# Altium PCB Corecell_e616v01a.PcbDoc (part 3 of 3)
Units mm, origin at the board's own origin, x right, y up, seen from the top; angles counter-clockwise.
Board outline 72.95 x 30.9 mm, 4 copper layers (Top Layer, MidLayer1 - GND, MidLayer2, Bottom Layer), stack 0.637 mm thick; 233 components, 174 nets, 666 pads, 1160 vias.
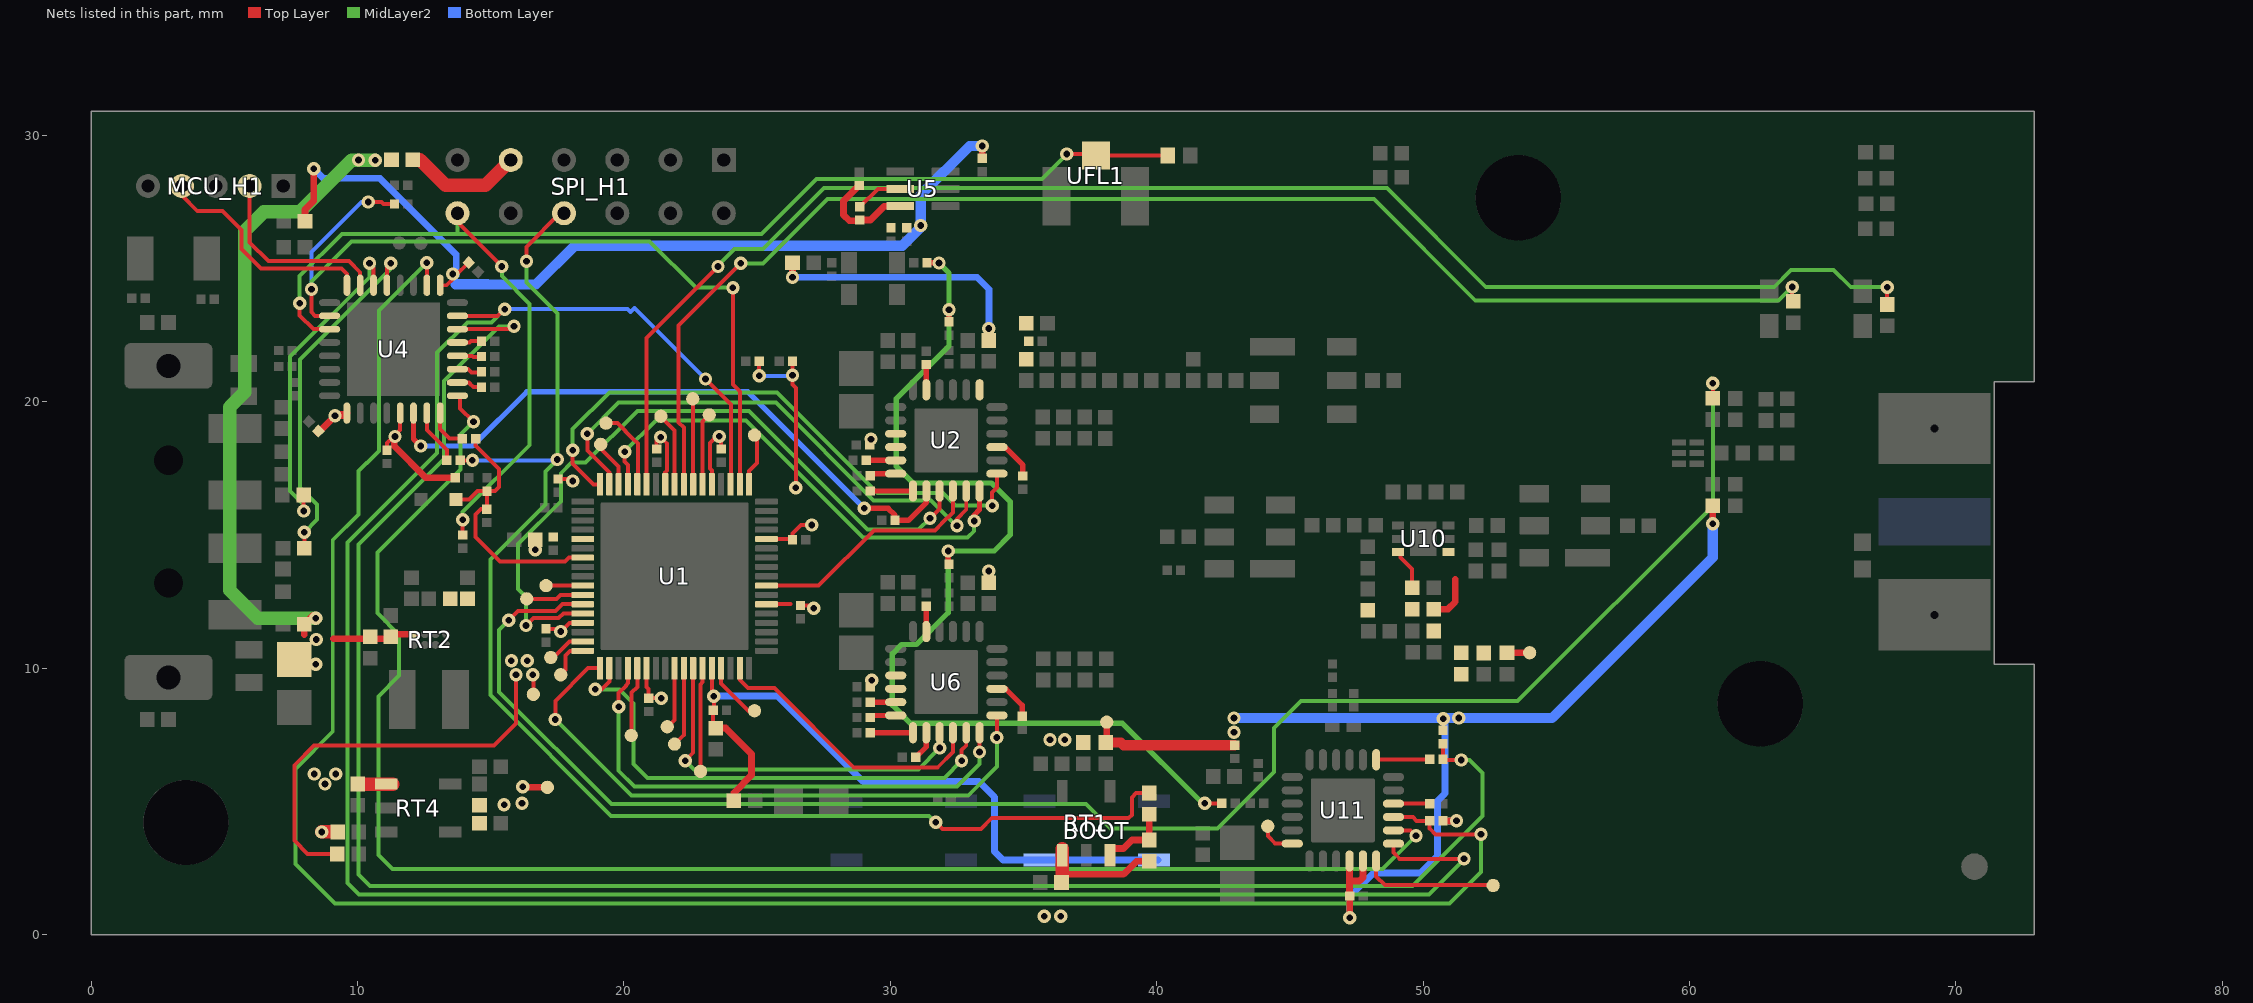
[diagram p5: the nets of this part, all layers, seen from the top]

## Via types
v1: diameter 0.5, hole 0.25, Top Layer to Bottom Layer, tented both sides, 1086 vias
v2: diameter 0.6, hole 0.3, Top Layer to Bottom Layer, tented top, 49 vias
v3: diameter 0.5, hole 0.25, Top Layer to Bottom Layer, 16 vias
v4: diameter 0.5, hole 0.2, Top Layer to Bottom Layer, 9 vias

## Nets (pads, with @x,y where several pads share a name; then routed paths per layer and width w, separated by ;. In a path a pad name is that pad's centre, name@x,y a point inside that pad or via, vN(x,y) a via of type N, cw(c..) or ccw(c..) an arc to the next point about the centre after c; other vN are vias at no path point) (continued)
NetR35_1: R35.1 U4.8 | length 1.6
  Top Layer w0.15: U4.8@13.1,19.575 13.1,18.975 13.457,18.618 R35.1@13.93,18.618
NetR37_2: R37.2 U4.13 | length 0.9
  Top Layer w0.15: U4.13@13.75,22.225 14.2,22.225 14.25,22.275 R37.2@14.65,22.275
NetR39_2: R39.2 R40.1 RT1.3 | length 2.6
  Top Layer w0.254: RT1.3@38.249,3.229 38.751,3.229 39.072,3.55 R39.2@39.717,3.55 R40.1@39.717,4.512
NetR48_1: R48.1 U4.10 | length 1
  Top Layer w0.15: U4.10@13.75,20.725 14.18,20.725 14.225,20.68 14.225,20.675 14.35,20.55 R48.1@14.65,20.55
NetR49_2: R49.2 U4.12 | length 0.9
  Top Layer w0.15: U4.12@13.75,21.725 14.3,21.725 14.35,21.675 14.625,21.675 R49.2@14.65,21.7
NetR50_1: R50.1 U4.11 | length 1
  Top Layer w0.15: U4.11@13.75,21.225 14.15,21.225 14.275,21.1 14.625,21.1 R50.1@14.65,21.125
NetR52_1: R52.1 U5.2 | length 1.8
  Top Layer w0.15: R52.1@28.854,27.325 28.863,27.325 29.531,27.993 U5.2@30.372,27.993
NetR55_1: R55.1 U4.7 | length 2.1
  Top Layer w0.15: U4.7@12.6,19.575 12.6,18.935 13.35,18.185 R55.1@13.35,17.8 R55.1@13.35,17.766
NetR56_1: R56.1 U11.19 | length 2
  Top Layer w0.15: U11.19@48.24,6.562 50.229,6.562 R56.1@50.245,6.579
NetR62_1: R62.1 U10.6 | length 1.5
  Top Layer w0.15: U10.6@49.159,14.356 49.159,14.149 49.589,13.718 R62.1@49.589,13.015
NetR63_1: R63.1 U11.16 | length 1.4
  Top Layer w0.15: U11.16@48.89,4.912 R63.1@50.25,4.912
NetRADIO_CTRL_0_1: RADIO_CTRL_0.1 U1.10 | length 1.4
  Top Layer w0.15: RADIO_CTRL_0.1@17.075,13.1 U1.10@18.45,13.1
NetRADIO_CTRL_4_1: RADIO_CTRL_4.1 U1.16 | length 1.4
  Top Layer w0.15: RADIO_CTRL_4.1@17.25,10.4 17.35,10.4 17.95,11 U1.16@18.45,11
NetRADIO_CTRL_5_1: RADIO_CTRL_5.1 U1.17 | length 1.5
  Top Layer w0.15: RADIO_CTRL_5.1@17.625,9.75 17.8,9.925 17.8,10.468 17.982,10.65 U1.17@18.45,10.65
NetRADIO_CTRL_6_1: RADIO_CTRL_6.1 U1.22 | length 2.6
  Top Layer w0.15: RADIO_CTRL_6.1@20.275,7.475 20.28,7.48 20.28,9.08 20.5,9.3 U1.22@20.5,10
NetRADIO_CTRL_7_1: RADIO_CTRL_7.1 U1.26 | length 2.3
  Top Layer w0.15: RADIO_CTRL_7.1@21.625,7.775 21.638,7.788 21.9,8.05 U1.26@21.9,10
NetRADIO_CTRL_8_1: RADIO_CTRL_8.1 U1.27 | length 3
  Top Layer w0.15: RADIO_CTRL_8.1@21.9,7.15 22.25,7.5 U1.27@22.25,10
NetRADIO_CTRL_10_1: RADIO_CTRL_10.1 U1.29 | length 3.9
  Top Layer w0.15: RADIO_CTRL_10.1@22.87,6.125 22.87,9.395 22.95,9.475 U1.29@22.95,10
NetRADIO_CTRL_11_1: RADIO_CTRL_11.1 U1.31 | length 2.3
  Top Layer w0.15: U1.31@23.65,10 23.65,9.417 24.667,8.4 RADIO_CTRL_11.1@24.9,8.4
NetSX1_DIO2_1: SX1_DIO2.1 U11.12 | length 5.2
  Top Layer w0.15: U11.12@48.24,2.762 48.24,2.18 48.565,1.854 52.476,1.854 52.559,1.772 SX1_DIO2.1@52.629,1.702
NetSX1_DIO3_1: SX1_DIO3.1 U11.6 | length 1.4
  Top Layer w0.15: SX1_DIO3.1@44.171,4.064 44.171,3.692 44.45,3.412 U11.6@45.09,3.412
NetSX1302_LNA_REG_EN_1: SX1302_LNA_REG_EN.1 U1.11 | length 2.2
  Top Layer w0.15: SX1302_LNA_REG_EN.1@16.35,12.6 17.475,12.6 17.625,12.75 U1.11@18.45,12.75
NetTP_GPIO0_1: TP_GPIO0.1 U1.66 | length 1.8
  Top Layer w0.15: TP_GPIO0.1@19.125,18.4 19.125,18.25 19.8,17.575 U1.66@19.8,16.9
NetTP_GPIO1_1: TP_GPIO1.1 U1.64 | length 3.1
  Top Layer w0.15: TP_GPIO1.1@19.325,19.2 19.75,19.2 20.055,18.895 20.055,18.891 20.316,18.63 20.324,18.63 20.52,18.434 20.52,16.92 U1.64@20.5,16.9
NetTP_GPIO3_1: TP_GPIO3.1 U1.60 | length 2.8
  Top Layer w0.15: TP_GPIO3.1@21.35,19.475 21.378,19.447 21.9,18.925 U1.60@21.9,16.9
NetTP_GPIO5_1: TP_GPIO5.1 U1.58 | length 3.2
  Top Layer w0.15: U1.58@22.6,16.9 TP_GPIO5.1@22.6,20.097
NetTP_GPIO6_1: TP_GPIO6.1 U1.57 | length 2.7
  Top Layer w0.15: U1.57@22.95,16.9 22.95,19.257 TP_GPIO6.1@23.2,19.507 ; TP_GPIO6.1@23.141,19.566 TP_GPIO6.1@23.15,19.575
NetTP_GPIO9_1: TP_GPIO9.1 U1.52 | length 2
  Top Layer w0.15: U1.52@24.7,16.875 U1.52@24.7,16.9 24.7,17.4 25,17.7 25,18.65 TP_GPIO9.1@24.9,18.75
POWER_SX1250_EN: R40.2 R55.2 SPI_H1.8 | length 51.7
  Top Layer w0.15: R55.2@13.85,17.8 v1(14.311,17.8) ; v1(16.342,25.273) 16.342,25.816 17.606,27.08 SPI_H1.8@17.75,27.08 ; v1(31.699,4.216) 31.953,3.962 33.4,3.962 33.807,4.37 38.948,4.37 39.065,4.487 39.065,5.153 39.224,5.312 R40.2@39.717,5.312
  MidLayer2 w0.15: v1(16.342,25.273) 16.342,24.478 17.5,23.32 17.5,17.875 17.478,17.853 17.45,17.825 17.45,17.775 17.053,17.377 17.053,16.146 14.986,14.079 14.986,8.992 19.519,4.458 31.457,4.458 v1(31.699,4.216)
  Bottom Layer w0.15: v1(14.311,17.8) 17.469,17.8 v1(17.5,17.831)
PPS: D11.1 R6.1 SPI_H1.12 U4.27 UFL1.3 | length 52.3
  Top Layer w0.15: v1(7.823,23.698) 7.823,23.241 8.339,22.725 U4.27@8.95,22.725 ; SPI_H1.12@13.75,27.08 13.75,26.746 v1(15.418,25.078) ; R6.1@13.945,14.997 v1(13.945,15.575) ; v1(36.627,29.3) UFL1.3@37.655,29.3 ; UFL1.3@37.713,29.242 D11.1@40.414,29.242
  MidLayer2 w0.15: v1(7.823,23.698) 7.823,24.714 9.409,26.3 13.725,26.3 ; SPI_H1.12@13.75,27.08 13.75,26.325 13.725,26.3 ; v1(13.945,15.575) 13.945,15.854 16.459,18.369 16.459,23.673 15.418,24.714 v1(15.418,25.078) ; v1(36.627,29.3) 35.698,28.371 27.228,28.371 25.157,26.3 13.725,26.3
RADIO_A_CLK_32M: R9.2 U2.14 U4.6 | length 24
  Top Layer w0.2: U4.6@12.1,19.575 12.1,18.61 v1(12.37,18.341) ; v1(29.025,16) 29.92,16 30.175,15.745 R9.2@30.175,15.55 30.682,15.55 31.35,16.218 U2.14@31.35,16.65
  Bottom Layer w0.2: v1(12.37,18.341) 14.316,18.341 16.35,20.375 24.65,20.375 v1(29.025,16)
RADIO_A_CLK_O: R4.2 U2.11 | length 0.9
  Top Layer w0.2: R4.2@29.25,17.8 U2.11@30.2,17.8
RADIO_A_CSN: U1.68 U2.19 | length 22
  Top Layer w0.15: v1(18.075,18.175) 18.075,17.675 18.85,16.9 U1.68@19.1,16.9 ; v1(33.825,16.1) 33.825,16.6 34,16.775 U2.19@34,17.3
  MidLayer2 w0.15: v1(18.075,18.175) 18.075,18.975 19.45,20.35 25.75,20.35 29.525,16.575 31.975,16.575 32.45,16.1 v1(33.825,16.1)
RADIO_A_IQ(0): R7.2 U2.13 | length 1.6
  Top Layer w0.2: R7.2@29.25,16.65 U2.13@30.85,16.65
RADIO_A_IQ(1): R5.2 U2.12 | length 1
  Top Layer w0.2: R5.2@29.25,17.225 29.325,17.3 U2.12@30.2,17.3
RADIO_A_IQ(2): R3.2 U2.5 | length 1
  Top Layer w0.2: U2.5@31.35,20.45 R3.2@31.35,21.4
RADIO_A_IQ(3): R10.2 U2.21 | length 1.7
  Top Layer w0.2: U2.21@34,18.3 34.301,18.3 34.976,17.625 R10.2@34.976,17.217
RADIO_A_MISO: U1.42 U2.16 | length 9
  Top Layer w0.15: U1.42@25.35,13.1 27.308,13.1 29.383,15.175 31.679,15.175 31.945,15.441 31.945,15.445 32.35,15.85 U2.16@32.35,16.65 U2.16@32.35,16.7
RADIO_A_MOSI: U1.67 U2.17 | length 20
  Top Layer w0.15: v1(18.625,18.8) 18.625,18.179 18.645,18.159 18.645,18.155 19.45,17.35 U1.67@19.45,16.9 ; v1(32.502,15.351) 32.502,15.602 32.85,15.95 U2.17@32.85,16.65
  MidLayer2 w0.15: v1(18.625,18.8) 19.8,19.975 25.7,19.975 29.375,16.3 31.525,16.3 v1@32.488,15.337
RADIO_A_NRESET: U1.13 U2.15 | length 26.8
  Top Layer w0.15: v1(16.325,11.6) 16.6,11.875 17.549,11.875 17.724,12.05 U1.13@18.45,12.05 ; v1(31.488,15.625) 31.5,15.625 31.85,15.975 U2.15@31.85,16.65
  MidLayer2 w0.15: v1(16.325,11.6) 16.325,12.675 16.025,12.975 16.025,14.653 17.628,16.256 17.628,17.303 18.038,17.712 18.563,17.712 20.5,19.65 24.7,19.65 29.15,15.2 31.063,15.2 v1(31.488,15.625)
RADIO_A_SCK: U1.65 U2.18 | length 18.4
  Top Layer w0.15: v1(20.025,18.125) 20.025,17.75 20.15,17.625 U1.65@20.15,16.9
  Top Layer w0.2: v1(33.15,15.525) 33.15,15.75 33.35,15.95 U2.18@33.35,16.65
  MidLayer2 w0.15: v1(20.025,18.125) 21.2,19.3 24.575,19.3 28.969,14.906 32.906,14.906 33.15,15.15 v1(33.15,15.525)
RADIO_B_CLK_32M: R16.1 U6.14 | length 1.1
  Top Layer w0.2: R16.1@30.95,6.65 31.35,7.05 U6.14@31.35,7.575
RADIO_B_CLK_O: R12.2 U6.11 | length 0.9
  Top Layer w0.2: R12.2@29.25,8.725 U6.11@30.2,8.725
RADIO_B_CSN: U1.18 U6.19 | length 23
  Top Layer w0.15: v1(17.425,8.075) 17.425,8.775 18.65,10 U1.18@19.1,10 ; v1(34,7.4) U6.19@34,8.225
  MidLayer2 w0.15: v1(17.425,8.075) 20.275,5.225 32.925,5.225 34,6.3 v1(34,7.4)
RADIO_B_IQ(0): R14.2 U6.13 | length 1.6
  Top Layer w0.2: R14.2@29.25,7.575 U6.13@30.85,7.575
RADIO_B_IQ(1): R13.2 U6.12 | length 1
  Top Layer w0.2: R13.2@29.25,8.15 29.325,8.225 U6.12@30.2,8.225
RADIO_B_IQ(2): R11.2 U6.5 | length 1
  Top Layer w0.2: U6.5@31.35,11.375 R11.2@31.35,12.325
RADIO_B_IQ(3): R15.1 U6.21 | length 1.6
  Top Layer w0.2: U6.21@34,9.225 34.332,9.225 34.95,8.607 R15.1@34.95,8.2
RADIO_B_MISO: U1.33 U6.16 | length 10.8
  Top Layer w0.15: U1.33@24.35,10 24.35,9.551 24.651,9.25 25.65,9.25 28.62,6.28 31.78,6.28 32.35,6.85 U6.16@32.35,7.575 U6.16@32.35,7.6
RADIO_B_MOSI: U1.19 U6.17 | length 19
  Top Layer w0.15: v1(18.926,9.205) 19.155,9.205 19.45,9.5 U1.19@19.45,10 ; v1(32.675,6.525) 32.675,6.925 32.85,7.1 U6.17@32.85,7.575
  MidLayer2 w0.15: v1(18.926,9.205) 19.824,9.205 20.35,8.679 20.35,6.4 20.875,5.875 32.025,5.875 v1(32.675,6.525)
RADIO_B_NRESET: U1.28 U6.15 | length 14.2
  Top Layer w0.15: v1(22.3,6.525) 22.6,6.825 U1.28@22.6,10 ; v1(31.85,7) U6.15@31.85,7.575
  MidLayer2 w0.15: v1(22.3,6.525) 22.625,6.2 31.05,6.2 v1(31.85,7)
RADIO_B_SCK: U1.21 U6.18 | length 19.3
  Top Layer w0.15: v1(19.801,8.55) 19.801,9.069 20.07,9.338 20.07,9.356 20.15,9.436 U1.21@20.15,10 ; v1(33.35,6.85) U6.18@33.35,7.575
  MidLayer2 w0.15: v1(19.801,8.55) 19.801,6.149 20.4,5.55 32.5,5.55 33.35,6.4 v1(33.35,6.85)
SWCLK: MCU_H1.4 U4.24 | length 8.6
  Top Layer w0.15: MCU_H1.4@3.405,28.1 3.405,27.743 3.981,27.167 4.928,27.167 5.639,26.456 5.639,25.73 6.366,25.003 9.402,25.003 9.6,24.805 U4.24@9.6,24.375
  Bottom Layer w0.15: MCU_H1.4@3.4,28.095 MCU_H1.4@3.405,28.1
SWDIO: MCU_H1.2 U4.23 | length 7.2
  Top Layer w0.15: MCU_H1.2@5.945,28.1 5.945,25.98 6.648,25.277 9.673,25.277 10.1,24.85 U4.23@10.1,24.375
SX1261_BUSY: U4.9 U11.14 | length 60.3
  Top Layer w0.15: U4.9@13.75,20.225 13.849,20.126 13.849,19.756 v1(14.352,19.253) ; U11.14@48.89,3.912 49.529,3.912 v1(49.733,3.708)
  MidLayer2 w0.15: v1(14.352,19.253) 13.866,18.768 13.866,17.616 13.868,17.613 13.868,17.462 10.744,14.338 10.744,12.065 11.557,11.252 11.557,9.716 10.778,8.937 10.778,2.98 11.303,2.455 48.48,2.455 v1(49.733,3.708)
SX1261_DIO1: U1.54 U4.15 U11.13 | length 85.3
  Top Layer w0.15: U4.15@13.75,23.225 15.249,23.225 15.499,23.475 v1(15.525,23.475) ; v1(23.063,20.853) 24.025,19.892 24.025,16.925 U1.54@24,16.9 ; U11.13@48.89,3.412 48.89,3.078 49.124,2.845 v1(51.537,2.845)
  MidLayer2 w0.15: v1(15.525,23.475) 15.032,22.982 14.118,22.982 12.979,21.844 12.979,18.085 9.62,14.725 9.62,1.937 10.058,1.499 50.216,1.499 51.537,2.819 v1(51.537,2.845)
  Bottom Layer w0.15: v1(15.525,23.475) 20.137,23.475 20.244,23.368 20.396,23.52 v1(23.063,20.853)
SX1261_NRESET: R65.2 U4.18 U11.15 | length 76.2
  Top Layer w0.15: U4.18@12.6,24.375 v1(12.6,25.223) ; U11.15@48.89,4.412 49.613,4.412 49.759,4.267 R65.2@50.25,4.267 50.25,3.979 50.47,3.759 v1(52.172,3.759)
  MidLayer2 w0.15: v1(12.6,25.223) 10.811,23.434 10.811,18.153 10.353,17.695 10.331,17.695 10.033,17.397 10.033,15.773 9.068,14.808 9.068,7.62 7.671,6.223 7.671,2.642 9.144,1.168 50.989,1.168 52.172,2.351 v1(52.172,3.759)
SX1261_NSS: R56.2 R64.2 U4.14 | length 72.9
  Top Layer w0.15: U4.14@13.75,22.725 15.765,22.725 v1(15.875,22.835) ; R64.2@50.75,7.167 50.745,7.162 R56.2@50.745,6.579 50.771,6.553 v1(51.435,6.553)
  MidLayer2 w0.15: v1(15.875,22.835) 15.31,22.835 13.249,20.774 13.249,17.853 10.033,14.637 10.033,2.261 10.465,1.829 49.606,1.829 52.222,4.445 52.222,6.073 51.742,6.553 v1(51.435,6.553)
SX1302_GPIO_8: R36.2 U1.53 U4.26 | length 32
  Top Layer w0.15: v1(8.269,24.225) 8.269,23.363 8.407,23.225 U4.26@8.95,23.225 ; v1(10.4,27.502) 10.892,27.502 10.968,27.426 R36.2@11.384,27.426 ; v1@24.122,24.315 v1(24.09,24.283) 24.09,20.65 24.35,20.391 U1.53@24.35,16.9
  MidLayer2 w0.15: v1(8.269,24.225) 8.269,24.515 9.779,26.025 20.963,26.025 22.704,24.283 v1(24.09,24.283) v1@24.207,24.283
  Bottom Layer w0.15: v1(8.269,24.225) 8.269,25.617 10.155,27.502 v1(10.4,27.502)
SX1302_RESET: C62.1 D5.2 R8.2 R35.2 U1.7 | length 10.5
  Top Layer w0.15: D5.2@13.7,16.332 14.184,16.332 14.496,16.645 C62.1@14.859,16.645 ; R35.2@14.43,18.618 14.43,18.365 15.316,17.479 15.316,16.804 15.158,16.645 C62.1@14.859,16.645 ; U1.7@18.45,14.15 17.94,14.15 17.795,14.005 15.344,14.005 14.43,14.919 14.43,15.769 14.63,15.969 R8.2@14.85,15.969 14.859,15.978 C62.1@14.859,16.645
SX1302_RX_ON: R20.1 U1.59 | length 52.3
  Top Layer w0.15: U1.59@22.25,16.9 22.25,19.031 22.05,19.231 22.05,22.872 24.374,25.197 v1(24.384,25.197) ; v1(63.856,24.308) 63.856,23.812 R20.1@63.9,23.768 R20.1@63.9,23.65
  MidLayer2 w0.15: v1(24.384,25.197) 25.222,25.197 27.635,27.61 48.149,27.61 51.959,23.8 63.348,23.8 v1(63.856,24.308)
SX1302_RXTX_SW: R18.2 U1.12 | length 64.9
  Top Layer w0.15: v1(15.675,11.8) 16.02,12.145 17.437,12.145 17.692,12.4 U1.12@18.45,12.4 ; R18.2@60.875,20.075 R18.2@60.875,20.136 v1(60.875,20.7)
  MidLayer2 w0.15: v1(15.675,11.8) 15.316,11.441 15.316,9.109 19.525,4.9 37.348,4.9 38.26,3.988 42.28,3.988 44.399,6.107 44.399,7.747 45.415,8.763 53.543,8.763 60.875,16.095 v1(60.875,20.7) ; v1@60.8,20.7 v1@60.8,20.875
SX1302_TX_ON: R21.2 U1.63 | length 57.1
  Top Layer w0.15: U1.63@20.85,16.9 20.85,22.4 v1(23.528,25.078) ; R21.2@67.425,23.65 v1(67.425,24.3)
  MidLayer2 w0.15: v1(23.528,25.078) 23.528,25.11 24.152,25.734 25.221,25.734 27.513,28.025 48.644,28.025 52.369,24.3 63.17,24.3 63.813,24.943 65.415,24.943 66.057,24.3 v1(67.425,24.3)
TCXO_32M_O: R19.2 R26.2 R27.1 R44.2 | length 39.6
  Top Layer w0.15: v1(41.808,4.928) R44.2@42.447,4.928
  Top Layer w0.2: R27.1@31.375,25.225 31.812,25.225 v1(31.825,25.212) ; v1(32.175,14.4) 32.175,13.925 R26.2@32.2,13.9 ; R19.2@32.2,23 v1(32.2,23.45) v1@32.2,23.475
  MidLayer2 w0.2: v1(31.825,25.212) 32.2,24.837 v1(32.2,23.45) 32.2,22.1 30.225,20.125 30.225,17.575 30.85,16.95 33.8,16.95 34.5,16.25 34.5,15 33.9,14.4 v1(32.175,14.4) 32.175,12.085 30.976,10.886 30.423,10.886 30.074,10.537 30.074,8.611 30.755,7.929 38.716,7.929 41.717,4.928 v1(41.808,4.928)
USB_DM: R45.2 U4.21 | length 13.5
  Top Layer w0.15: R45.2@8,14.5 v1(8,15.1) ; U4.21@11.1,24.375 11.1,25.05 v1(11.25,25.2)
  MidLayer2 w0.15: v1(8,15.1) 8.475,15.575 8.475,16.15 7.845,16.78 7.845,21.595 11.25,25 v1(11.25,25.2)
USB_DP: R46.2 U4.22 | length 12.2
  Top Layer w0.15: v1(7.975,15.9) R46.2@7.975,16.5 ; v1(10.45,25.2) 10.6,25.05 U4.22@10.6,24.375
  MidLayer2 w0.15: v1(7.975,15.9) 7.975,16.15 7.468,16.657 7.468,21.693 10.45,24.675 v1(10.45,25.2)
VCC5V: C15.1 C16.1 C51.1 C59.1 FB2.1 FB4.2 R23.1 R39.1 R43.1 RT1.1 RT2.A2 RT4.1 | length 34.1
  Top Layer w0.25: C16.1@11.25,11.175 C16.1@11.35,11.275
  Top Layer w0.254: 8,11.25 FB4.2@8,11.65 8.325,11.975 v1(8.425,11.875) ; 9.1,11.1 10.475,11.1 11.25,11.1 C16.1@11.275,11.1 ; C16.1@11.35,11.275 RT2.A2@12.125,11.275 ; 36.449,2.261 38.746,2.261 39.235,2.75 R39.1@39.717,2.75
  Top Layer w0.508: v1(8.65,3.85) R43.1@9.25,3.85 ; C59.1@10,5.65 RT4.1@11.073,5.65 RT4.1@11.325,5.65 ; C51.1@36.428,1.956 36.449,1.977 36.449,2.261 RT1.1@36.449,2.977 RT1.1@36.449,3.229
  MidLayer2 w0.508: v1(8.425,11.875) 6.25,11.875 5.201,12.924 5.201,19.801 5.766,20.366 5.766,26.415 6.478,27.127 7.832,27.127 9.78,29.075 v1(10.033,29.075) v1@10.65,29.075
  other v1: 35.775,0.686 36.398,0.686 8.775,5.65 8.375,6.025 9.175,6.025 8.425,10.15 8.45,11.075 10.668,29.071
VCC5V_EXT: FB2.2 SPI_H1.9 | length 4.5
  Top Layer w0.508: FB2.2@12.075,29.087 12.339,29.087 13.305,28.122 14.792,28.122 SPI_H1.9@15.75,29.08
VCCCORE12: C2.2 C4.2 C5.2 C6.2 C8.2 C53.2 FB3.2 R22.2 U1.5 U1.23 U1.40 U1.56 VCCCORE12.1 | length 21.8
  Top Layer w0.15: R22.2@9.243,3.023 8.128,3.023 7.625,3.526 7.625,6.355 8.37,7.1 15.125,7.1 15.95,7.925 v1(15.95,9.75) ; v1(16.575,9.75) 16.6,9.725 VCCCORE12.1@16.6,9.018 ; U1.23@20.85,10 20.85,9.3 20.925,9.225 C8.2@20.925,8.875 v1(21.4,8.875) ; U1.56@23.3,16.9 23.3,17.425 23.225,17.5 23.225,18.45 23.475,18.7 v1(23.575,18.7) 23.65,18.625 C2.2@23.65,18.3 ; v1@23.65,18.7 v1@23.65,18.725 ; U1.40@25.35,12.4 26.25,12.4 ; C6.2@26.6,12.325 C6.2@26.625,12.35 27,12.35 v1@27.1,12.25
  other v1: 15.775,10.275 16.375,10.275 27.125,12.25 16.675,14.45
VCCIO33: BOOT.1 C1.2 C3.2 C7.2 C9.2 C10.2 C12.2 C13.2 C38.1 C40.1 C54.2 C55.2 FB1.2 FB14.2 R1.2 R29.2 R31.2 R32.2 R33.2 R42.1 R51.2 R52.2 U1.14 U1.30 U1.47 U1.61 U4.1 U4.5 U4.17 U5.3 VCCIO33.1 | length 85.7
  Top Layer w0.15: 8.827,19.123 8.827,19.148 ; v1(9.154,19.475) 9.254,19.575 U4.1@9.6,19.575 ; C13.2@11.104,18.085 C13.2@11.104,18.182 11.104,18.451 11.376,18.723 11.6,18.947 U4.5@11.6,19.575 ; U4.17@13.1,24.375 13.346,24.375 13.575,24.604 v1@13.575,24.629 ; v1(13.575,24.8) v1@13.575,24.629 ; C54.2@14.173,25.227 13.661,24.714 v1@13.575,24.629 ; C7.2@17.075,11.475 17.525,11.475 v1(17.625,11.375) 17.95,11.7 U1.14@18.45,11.7 ; R1.2@17.525,17.1 18,17.1 v1(18.075,17.025) ; C1.2@21.225,18.225 21.225,18.525 v1(21.375,18.675) 21.625,18.425 21.625,17.422 21.55,17.347 U1.61@21.55,16.9 ; U1.30@23.3,10 23.3,9.025 v1(23.375,8.95) 23.375,8.45 C9.2@23.35,8.425 23.35,7.85 C10.2@23.45,7.75 ; v1(25.075,20.975) R31.2@25.075,21.525 ; U1.47@25.35,14.85 26.3,14.85 C3.2@26.325,14.825 26.325,15.05 26.65,15.375 v1(27.05,15.375) ; R33.2@26.325,21.525 v1(26.325,21) 26.325,20.65 26.45,20.525 v1(26.45,16.775)
  Top Layer w0.254: FB1.2@8.025,26.775 8.025,27.222 8.357,27.553 v1(8.357,28.752) ; C12.2@8.518,18.839 8.552,18.873 8.827,19.148 v1(9.154,19.475) 9.5,19.475 U4.1@9.6,19.575 ; v1@11.376,18.723 11.376,18.694 11.376,18.338 12.569,17.145 R32.2@13.669,17.145 ; v1(16.2,5.55) 16.225,5.525 VCCIO33.1@17.125,5.525 ; C10.2@23.45,7.75 23.826,7.75 23.853,7.723 23.853,7.719 24.79,6.782 24.79,5.985 24.125,5.32 R42.1@24.125,5.025 ; R29.2@28.831,28.122 28.245,27.535 28.245,27.014 28.458,26.8 28.83,26.8 R52.2@28.854,26.825 29.259,26.825 29.777,27.343 U5.3@30.372,27.343 ; R51.2@33.447,29.138 v1(33.447,29.605)
  Bottom Layer w0.15: v1(25.075,20.975) 26.3,20.975 v1(26.325,21)
  Bottom Layer w0.254: v1(8.357,28.752) 8.72,28.388 10.838,28.388 13.7,25.526 13.7,24.8 13.7,24.729 13.629,24.8 v1(13.575,24.8) ; v1(23.375,8.95) 25.772,8.95 28.981,5.74 33.325,5.74 33.909,5.156 33.909,3.116 34.225,2.8 BOOT.1@35.6,2.8 BOOT.1@39.9,2.8 BOOT.1@40.05,2.8
  Bottom Layer w0.381: 13.675,24.41 14.882,24.41 14.883,24.409 16.701,24.409 18.147,25.855 30.445,25.855 31.14,26.551 v1(31.14,26.619) 31.14,27.768 32.977,29.605 v1(33.447,29.605)
  other v1: 15.5,4.875 16.175,4.925 11.405,18.694
VDD_RF_1250: C37.2 C47.2 C50.2 C75.2 FB5.1 FB8.2 FB12.2 R17.1 R24.2 R25.1 R41.1 R64.1 R65.1 U2.9 U2.10 U6.9 U6.10 U11.10 U11.11 VDD_RF_1250.1 | length 52.2
  Top Layer w0.254: v1(26.325,24.675) FB5.1@26.325,25.225 ; C50.2@38.09,7.209 38.125,7.245 VDD_RF_1250.1@38.125,7.976 ; U11.10@47.24,2.762 47.24,2.007 ; v1(47.248,0.635) C75.2@47.248,1.448 47.24,1.456 47.24,2.007 ; U11.11@47.74,2.762 47.74,2.14 47.607,2.007 47.24,2.007 ; R65.1@50.75,4.267 v1(51.257,4.267) ; v1(60.875,15.425) R24.2@60.875,16.1
  Top Layer w0.381: C50.2@38.09,7.209 38.659,7.209 38.76,7.108 R41.1@42.926,7.108
  Bottom Layer w0.254: v1@26.3,24.675 v1(26.325,24.675) 33.25,24.675 33.7,24.225 v1(33.7,22.75) ; v1(47.248,0.635) 47.248,1.425 48.134,2.311 49.911,2.311 50.546,2.946 50.546,4.267 ; v1@50.825,8.078 50.825,5.3 50.546,5.021 50.546,4.267 ; v1(51.257,4.267) 50.546,4.267
  Bottom Layer w0.381: v1(42.901,8.128) 50.754,8.128 v1@50.875,8.128 ; v1@50.825,8.078 v1@50.875,8.128 ; v1(60.875,15.425) 60.875,14.157 54.846,8.128 v1(51.333,8.128) v1@50.875,8.128
  other v1: 35.992,7.315 36.551,7.315 42.901,7.6 50.754,8.1 29.3,9.55 33.7,13.65 29.275,18.6
VDD_RF_LNA: C14.2 C61.2 C68.1 FB8.1 R60.2 R61.2 R62.2 U10.1 VDD_RF_LNA.1 | length 2.6
  Top Layer w0.254: C68.1@50.398,12.215 50.933,12.215 51.206,12.489 51.206,13.335 ; C61.2@53.15,10.577 VDD_RF_LNA.1@54,10.577
VR_PA: C17.2 C18.2 L1.2 U2.1
pads on no net: "Fiducial Mark1.1" RT1.4 RT4.4 SCREW-1.1 SCREW-2.1 SCREW-3.1 U2.4 U6.1 U6.4 U6.24 U11.4 U11.23 U11.24 USB_DC_IN1.NPTH1 USB_DC_IN1.NPTH2
copper on no net:
  other v1: 4.7,6.775

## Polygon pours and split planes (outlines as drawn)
GND on MidLayer1 - GND "GND_L02_P006" (solid, remove dead copper, pour order 6): 0,30.9 72.95,30.9 72.95,0 0,0
GND on MidLayer2 "GND_L03_P008" (solid, remove dead copper, pour order 8): 0,30.9 72.936,30.9 72.95,30.886 72.95,0.001 72.949,0 0,0
GND on Bottom Layer "GND_L04_P010" (solid, remove dead copper, pour order 10): 0,30.9 72.95,30.9 72.95,0 0,0
GND on Top Layer "GND_L01_P012" (solid, remove dead copper, pour order 12): 0,30.9 72.95,30.9 72.95,0.001 72.949,0 0,0

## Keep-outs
Keep-Out Layer:
  the board outline again, w0.05

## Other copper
Top Layer:
  rectangle net VCC5V: 9.728,28.737 11.562,29.388
  rectangle net VDD_RF_LNA: 51.13,10.487 51.74,11.675
  rectangle net VDD_RF_LNA: 51.156,10.275 53.416,10.875
  rectangle net VDD_RF_1250: 35.65,6.934 38.379,7.569
  rectangle net GND: 5.2,21.125 6.25,22.675
  rectangle net GND: 7.225,19.475 8.025,20.075
  rectangle net GND: 6.575,19.475 7.375,20.6
  rectangle net NetD4_1: 6,18.625 7.425,19.275
  rectangle net NetD4_1: 5.225,19.15 6.225,20.525
  rectangle net NetD6_1: 5.4,10.375 6.45,11.875
  rectangle net GND: 5.575,7.875 7.125,9.175
  rectangle net NetD6_1: 6.175,11.325 7.475,12.425
  rectangle net GND: 5.425,7.875 6.425,9.775
  rectangle net NetC52_2: 11.75,12.325 12.775,12.875
  rectangle net NetC52_2: 12.425,12.725 12.95,13.975
  rectangle net NetC52_2: 13.175,9.8 14.175,10.5
  rectangle net VCCCORE12: 13.2,12.3 15.15,12.925
  rectangle net VCCCORE12: 14.475,10.025 15.15,12.9
  rectangle net VCCCORE12: 14.475,9.475 16.875,10.525
  rectangle net NetC52_2: 12.4,11.95 12.95,12.375
  rectangle net GND: 10.975,11.85 11.625,13.675
  rectangle net GND: 10.975,13.075 12.3,13.675
  rectangle net GND: 5.425,6.55 6.925,8.5
  rectangle net VCC5V: 8.125,5.375 11.775,6.275
  rectangle net GND: 9.7,4.5 12.625,5.125
  rectangle net NetC58_1: 12.8,5.375 14.875,6.625
  rectangle net VCCIO33: 14.3,4.6 16.55,5.125
  rectangle net VCCIO33: 15.825,4.6 16.55,5.85
  rectangle net VCCIO33: 14.3,3.9 14.85,5.125
  rectangle net NetFB15_2: 2.625,7.8 3.2,10.1
  rectangle net GND: 1.1,7.8 2.4,8.375
  rectangle net NetFB6_2: 2.6,20.775 3.2,23.25
  rectangle net GND: 1.125,22.7 2.4,23.25
  rectangle net VDD_RF_LNA: 48.031,11.905 50.673,12.444
  rectangle net VDD_RF_LNA: 50.114,11.1 50.673,12.421
  rectangle net VDD_RF_LNA: 50.114,11.1 51.74,11.675
  rectangle net GND: 49.5,15.046 50.5,16.15
  rectangle net VCCIO33: 29.847,26.365 30.912,27.432
  rectangle net VCCIO33: 30.353,26.365 31.496,26.983
  rectangle net VDD_RF_1250: 42.676,6.934 43.129,8.363
  rectangle net VCC5V: 36.139,0.33 36.703,3.658
  rectangle net VCC5V: 35.509,0.33 36.703,1.067
  rectangle net NetC49_1: 36.153,6.125 37.49,6.68
  rectangle net NetC49_1: 36.144,4.648 36.762,6.672
  rectangle net VDD_RF_1250: 51.16,7.95 51.729,10.033
  rectangle net VDD_RF_1250: 50.521,7.849 51.729,8.357
  rectangle net VDD_RF_1250: 50.521,7.493 50.952,8.325
  rectangle net GND: 52,9.5 53.416,10.033
  region net GND: 15.138,15.672 15.685,15.125 16.18,15.125 16.18,14.475 15.573,14.475 15.443,14.605 15.128,14.605 14.65,15.083 14.65,15.672
  pour cut-out: 10.414,4.521 10.414,4.089 12.371,4.089 12.388,4.072 12.4,4.084 12.4,4.5
  pour cut-out: 40.742,14.397 40.923,14.397 40.919,14.394 40.919,13.981 40.766,13.981 40.742,14.005
  pour cut-out: 61.367,18.455 61.827,18.454 61.827,18.603 61.365,18.603
  pour cut-out: 53.066,15.732 53.527,15.732 53.527,15.88 53.064,15.88
  pour cut-out: 59.076,15.129 59.141,15.081 58.965,14.955 58.935,14.975
  pour cut-out: 38.574,19.682 38.715,19.557 38.67,19.499 38.637,19.499 38.533,19.602
  pour cut-out: 45.435,14.686 45.488,14.659 45.54,14.632 45.42,14.501 45.368,14.553
  pour cut-out: 36.733,18.23 37.018,18.23 37.018,18.273 36.733,18.273
  pour cut-out: 35.956,18.228 36.241,18.228 36.241,18.271 35.956,18.271
  pour cut-out: 37.553,10.841 37.838,10.841 37.838,10.884 37.553,10.884
  pour cut-out: 35.973,10.842 36.258,10.841 36.258,10.884 35.973,10.884
  pour cut-out: 36.758,10.843 37.043,10.843 37.043,10.886 36.758,10.886
  pour cut-out: 36.758,9.15 37.043,9.15 37.043,9.193 36.758,9.193
  pour cut-out: 35.985,9.153 36.27,9.153 36.27,9.196 35.985,9.196
  pour cut-out: 49.926,16.21 50.211,16.21 50.211,16.253 49.926,16.253
  pour cut-out: 49.123,16.184 49.407,16.184 49.407,16.227 49.122,16.227
  pour cut-out: 41.441,15.415 41.725,15.415 41.725,15.458 41.44,15.458
  pour cut-out: 41.444,14.4 41.729,14.4 41.729,14.443 41.443,14.443
  pour cut-out: 46.88,15.851 47.165,15.851 47.165,15.894 46.88,15.894
  pour cut-out: 46.099,15.853 46.383,15.853 46.383,15.895 46.098,15.895
  pour cut-out: 46.088,14.839 46.373,14.839 46.373,14.882 46.088,14.882
  pour cut-out: 46.878,14.837 47.162,14.837 47.162,14.879 46.877,14.879
  pour cut-out: 53.206,14.77 53.667,14.77 53.667,14.919 53.204,14.919
  pour cut-out: 63.121,17.546 63.405,17.546 63.405,17.589 63.12,17.589
  pour cut-out: 62.283,17.55 62.62,17.55 62.62,17.618 62.282,17.618
  pour cut-out: 61.448,17.548 61.732,17.548 61.732,17.591 61.447,17.591
  pour cut-out: 58.695,15.834 58.979,15.834 58.979,15.877 58.694,15.877
  pour cut-out: 57.935,15.834 58.22,15.834 58.22,15.877 57.934,15.877
  pour cut-out: 57.133,15.791 57.417,15.79 57.417,15.879 57.132,15.879
  pour cut-out: 57.081,14.832 57.365,14.832 57.365,14.902 57.08,14.902
  pour cut-out: 57.915,14.824 58.199,14.824 58.199,14.867 57.914,14.867
  pour cut-out: 48.363,21.283 48.647,21.283 48.647,21.326 48.362,21.326
  pour cut-out: 47.583,21.281 47.868,21.281 47.868,21.324 47.583,21.324
  pour cut-out: 48.349,20.274 48.633,20.274 48.633,20.317 48.348,20.317
  pour cut-out: 47.539,20.278 47.823,20.278 47.823,20.321 47.538,20.321
  pour cut-out: 43.173,21.287 43.458,21.287 43.458,21.329 43.173,21.329
  pour cut-out: 42.442,21.285 42.726,21.284 42.726,21.327 42.441,21.327
  pour cut-out: 40.064,21.285 40.348,21.285 40.348,21.328 40.063,21.328
  pour cut-out: 39.281,21.286 39.566,21.285 39.566,21.328 39.281,21.328
  pour cut-out: 38.485,21.286 38.77,21.285 38.77,21.328 38.484,21.328
  pour cut-out: 37.572,19.916 37.856,19.916 37.856,19.959 37.571,19.959
  pour cut-out: 36.762,19.916 37.047,19.916 37.047,19.959 36.762,19.959
  pour cut-out: 35.969,19.915 36.254,19.915 36.253,19.958 35.968,19.958
  pour cut-out: 43.168,20.269 43.453,20.268 43.453,20.311 43.168,20.311
  pour cut-out: 42.405,20.273 42.69,20.272 42.69,20.315 42.405,20.315
  pour cut-out: 41.618,20.271 41.903,20.27 41.903,20.313 41.618,20.313
  pour cut-out: 40.839,20.27 41.124,20.27 41.124,20.313 40.839,20.313
  pour cut-out: 40.048,20.272 40.333,20.272 40.333,20.315 40.048,20.315
  pour cut-out: 39.269,20.271 39.554,20.271 39.554,20.314 39.269,20.314
  pour cut-out: 38.471,20.27 38.756,20.27 38.756,20.313 38.471,20.313
  pour cut-out: 37.681,20.271 37.965,20.271 37.965,20.314 37.68,20.314
  pour cut-out: 36.911,20.27 37.195,20.27 37.195,20.313 36.91,20.313
  pour cut-out: 36.139,20.271 36.424,20.27 36.424,20.313 36.139,20.313
  region net GND: 8.975,20.35 9.35,20.35 9.85,20.85 9.85,20.1 8.975,20.1
  region net GND: 8.15,19 9.325,20.175 9.325,20.35 7.475,20.35 7.475,19.675
  region net GND: 12.875,23.8 12.875,23.475 13.3,23.475 13.3,23.8
  region net GND: 13.1,23.6 13.575,23.6 13.575,24.075
  region net VCCIO33: 14.025,25.65 14.425,25.25 14.425,25.225 13.2,24 12.95,24 12.95,24.575
  region net GND: 14.525,25.125 14.775,24.875 14.775,24.85 14.175,24.25 14.175,23.475 13.175,23.475 13.175,23.65 13.425,23.9 13.575,23.9 13.575,24.075 14.275,24.775 14.275,24.875
  region net GND: 34.3,8.925 34.425,8.8 34.425,8.65 34.3,8.525 33.125,8.525 33.15,8.55 33.15,8.925
  region net GND: 29.775,10.925 30.625,10.925 31.2,10.35 31.2,9.975 30.625,10.55 29.775,10.55
  region net GND: 34.266,18 34.404,17.862 34.404,17.729 34.275,17.6 33.1,17.6 33.125,17.625 33.125,18
  region net GND: 29.925,19.975 30.675,19.975 31.3,19.35 31.15,19.2 31.05,19.2 30.65,19.6 29.725,19.6 29.725,19.925 29.725,19.975
  region net GND: 23.675,8.65 23.975,8.65 24.625,8 24.625,7.8 24.45,7.625 24.3,7.625 23.675,8.25
  region net GND: 20.725,8.55 21.1,8.55 21.1,8.2 21.2,8.1 21.2,7.8 21.1,7.7 20.75,7.7 20.65,7.8 20.65,8.125 20.725,8.2
  region net GND: 17.25,11.15 16.875,11.15 16.8,11.225 16.425,11.225 16.3,11.1 16.3,10.775 16.4,10.675 16.8,10.675 16.925,10.8 17.25,10.8
  region net GND: 26.8,12.025 26.8,11.65 26.45,11.65 26.175,11.925 26.175,12.15 26.3,12.15 26.425,12.025
  region net GND: 25.725,14.525 26.556,14.525 26.644,14.613 26.644,15 27.044,15 27.044,14.563 26.856,14.375 25.725,14.4
  region net GND: 23.475,17.9 23.825,17.9 23.825,17.55 23.75,17.475 23.75,17.275 23.55,17.275 23.55,17.475 23.475,17.55
  region net GND: 21.05,17.9 21.4,17.9 21.4,17.55 21.3,17.5 21.3,17.3 21.1,17.3 21.1,17.5 21.05,17.55
  region net VCCCORE12: 25.75,12.5 27.35,12.5 27.425,12.425 27.425,12.125 27.275,11.975 27.025,11.975 26.7,12.3 25.75,12.3
  region net VCCCORE12: 20.75,9.638 20.75,8.7 21.15,8.7 21.27,8.6 21.55,8.6 21.7,8.75 21.7,9.013 21.525,9.188 21.1,9.188 20.95,9.338 20.95,9.638
  region net VCCIO33: 25.75,14.95 26.15,14.95 26.15,15 26.8,15.65 26.95,15.65 27.225,15.65 27.325,15.55 27.325,15.275 27.175,15.125 26.525,15.125 26.5,15.1 26.5,14.65 26.15,14.65 26.15,14.775 25.75,14.775
  region net VCCIO33: 18.05,11.8 17.825,11.8 17.675,11.65 16.9,11.65 16.9,11.3 17.275,11.3 17.45,11.125 17.75,11.125 17.9,11.275 17.9,11.525 18.05,11.675
  region net VCCIO33: 17.5,17.3 18.15,17.3 18.35,17.1 18.35,16.825 18.275,16.75 17.975,16.75 17.8,16.925 17.35,16.925 17.35,17.3
  region net VCCIO33: 23.2,9.6 23.2,9.225 23.125,9.15 23.125,7.925 23.525,7.925 23.525,8.675 23.7,8.85 23.7,9.05 23.4,9.35 23.4,9.6
  region net VCCCORE12: 23.7,18.95 23.825,18.825 23.825,18.05 23.325,18.05 23.325,18.875 23.4,18.95
  region net VCCIO33: 21.05,18.925 21.575,18.925 21.675,18.825 21.675,18.05 21.05,18.05
  region net VCC5V: 7.725,12.3 8.814,12.3 8.814,9.675 7.725,9.675 7.725,9.75
  region net VDD_RF_1250: 33.425,12.925 33.975,12.925 33.975,13.75 33.825,13.9 33.575,13.9 33.425,13.75
  region net NetC41_2: 30.175,13.5 29.375,13.5 29.225,13.35 29.225,13.1 29.375,12.95 30.175,12.95
  region net NetC41_2: 33,11.35 33,11.875 33.175,12.05 33.175,13.75 33.025,13.9 32.775,13.9 32.625,13.75 32.625,11.95 32.7,11.875 32.7,11.35
  region net NetC46_2: 31,11.375 31,12.7 29.5,12.7 29.375,12.825 28.725,12.825 28.725,12.15 30.4,12.15 30.7,11.85 30.7,11.375
  region net NetL10_2: 30.2,10.375 30.2,10.075 29.525,10.075 29.375,9.925 28.725,9.925 28.725,10.6 29.375,10.6 29.6,10.375
  region net VR_PA: 33.35,20.2 33.95,20.2 34.6,20.85 34.6,21.25 34.675,21.325 34.75,21.325 35.15,21.325 35.15,22.125 34.925,22.125 34.725,21.925 34.646,21.925 34.1,21.379 34.1,21.075 33.725,20.7 33.35,20.7
  region: 30.35,10.7
  region net VDD_RF_1250: 33.425,22.025 33.975,22.025 33.975,22.85 33.825,23 33.575,23 33.425,22.85
  region net VR_PA: 34.825,21.325 35.375,21.325 35.375,23.225 34.825,23.225
  region net NetC23_2: 33,20.45 33,20.975 33.175,21.15 33.175,22.85 33.025,23 32.775,23 32.625,22.85 32.625,21.05 32.7,20.975 32.7,20.45
  region net NetC23_2: 30.175,22.575 29.375,22.575 29.225,22.425 29.225,22.175 29.375,22.025 30.175,22.025
  region net NetC36_2: 31,20.45 31,21.775 29.5,21.775 29.375,21.9 28.725,21.9 28.725,21.225 30.4,21.225 30.7,20.925 30.7,20.45
  region net NetL7_2: 30.2,19.45 30.2,19.15 29.525,19.15 28.725,19.15 28.725,19.675 29.375,19.675 29.6,19.45
  region net VDD_RF_1250: 30.2,18.95 29.6,18.95 29.5,18.85 29.125,18.85 29.05,18.775 29.05,18.15 30.2,18.15 30.2,18.45 30.1,18.45 30.1,18.65 30.2,18.65
  region net VDD_RF_1250: 30.2,9.875 29.6,9.875 29.5,9.775 29.125,9.775 29.05,9.7 29.05,9.075 30.2,9.075 30.2,9.375 30.1,9.375 30.1,9.575 30.2,9.575
  region net VCCCORE12: 18.415,14.735 18.415,14.965 17.82,14.965 17.685,15.1 16.4,15.1 16.4,14.42 16.57,14.25 16.775,14.25 16.95,14.425 16.95,14.655 17.045,14.75 17.385,14.75 17.55,14.75 17.565,14.765 17.765,14.765 17.795,14.735
  region net VCC5V: 8.8,11.525 11.65,11.525 11.65,10.875 11.475,10.875 8.8,10.875
  pour cut-out: 69.475,1.375 72.737,1.375 72.737,0.25 69.475,0.25
  region net VDD_RF_LNA: 50.733,14.34 51.184,14.34 51.184,13.642 51.391,13.434 51.391,12.49 50.93,12.028 50.578,12.028 50.35,12.027 50.35,12.487 50.753,12.488 50.982,12.717 50.982,13.182 50.733,13.539
  region net VCCIO33: 10.922,18.085 10.922,18.596 11.311,18.986 11.417,19.092 11.445,19.982 11.491,20.029 11.711,20.029 11.786,19.954 11.786,18.644 11.592,18.45 11.278,18.388 11.278,18.085
  text "1" at 69.825,0.4 h0.76
MidLayer1 - GND:
  pour cut-out: 69.5,1.35 72.75,1.35 72.75,0.225 69.5,0.225
  text "2" at 70.4,0.4 h0.76
MidLayer2:
  rectangle net VCC5V: 9.728,28.737 10.922,29.392
  region net VCCCORE12: 21,8.4 21.8,8.4 21.8,9.8 25.85,9.8 25.85,11.85 27.625,11.85 27.625,12.55 25.175,12.55 25.175,10.45 21,10.45
  region net VCCCORE12: 23.225,19.075 23.95,19.075 23.95,16.525 18.925,16.525 18.925,14.15 16.4,14.15 16.4,14.75 18.45,14.75 18.45,17.1 19.9,17.124 23.225,17.124
  region net VCCCORE12: 18.275,14.15 18.925,14.15 18.925,10.45 18.925,9.725 18.2,9.725 18.2,14.15
  region net VCCCORE12: 23.225,17.124 25.85,17.124 25.85,12.375 25.175,12.375 25.175,16.525 23.225,16.525
  region net VCCCORE12: 15.525,10.525 18.875,10.525 18.875,9.725 16.875,9.725 16.875,9.475 15.525,9.475
  pour cut-out: 69.5,1.325 72.725,1.325 72.725,0.2 69.5,0.2
  text "3" at 71.2,0.4 h0.76
Bottom Layer:
  rectangle net VDD_RF_1250: 42.621,7.325 43.155,8.4
  rectangle net VDD_RF_1250: 34.5,6.934 36.875,7.569
  rectangle net VDD_RF_1250: 34.5,7.137 35.001,8.3
  rectangle net VDD_RF_1250: 33.553,7.925 35.001,8.3
  rectangle net NetC23_2: 29.208,21.65 29.775,22.567
  rectangle net NetC23_2: 29.225,21.575 33.225,22.05
  rectangle net VCC5V: 8.125,1.475 9.4,12.15
  rectangle net VCCIO33: 15.1,4.6 16.55,5.175
  rectangle net VCCIO33: 15.825,4.6 16.55,9.114
  rectangle net VCCIO33: 17.125,8.7 18.25,12.066
  rectangle net VCC5V: 8.125,1.35 36.703,2.3
  rectangle net VDD_RF_1250: 33.528,7.938 34.036,11.975
  rectangle net VCC5V: 35.509,0.33 36.703,2.306
  rectangle net VCCIO33: 15.825,8.458 18.25,9.246
  region net VCCIO33: 13.025,25.1 13.945,25.1 13.945,19.65 10.811,19.65 10.811,20.136 13.233,20.136 13.233,23.95 13.025,23.95
  region net VCCIO33: 17.1,17.35 20.95,17.35 20.95,19.1 21.825,19.1 21.825,16.675 21.825,16.625 17.1,16.625
  region net VCCIO33: 17.125,11.775 18.25,11.775 18.25,10.35 23.775,10.35 23.775,8.575 23.025,8.575 23.025,9.875 18.25,9.875 17.125,9.875
  region net VCCIO33: 8.8,19.85 11.709,19.85 11.709,17.567 11.074,17.567 11.074,19.075 8.8,19.075
  region net VCCIO33: 21.251,17.35 26.75,17.35 26.75,15.8 27.425,15.8 27.425,15 25.975,15 25.975,16.625 21.251,16.625
  region net VCCIO33: 17.1,16.675 17.1,11.6 18.25,11.6 18.25,16.675
  region net VCCIO33: 11.074,18.009 11.711,18.009 11.711,16.916 17.597,16.916 17.597,16.325 11.074,16.325
  region net NetC23_2: 32.6,22.6 32.6,23.225 33.225,23.225 33.225,21.65 32.6,21.65
  region net NetC41_2: 32.625,13.925 33.175,13.925 33.175,12.95 29.15,12.95 29.15,13 29.15,13.05 29.15,13.525 32.625,13.525
  region net VDD_RF_1250: 34.05,23.05 34.05,20.05 30.4,20.05 30.4,18.3 28.85,18.3 28.85,19 29.725,19 29.725,20.625 33.4,20.625 33.4,23.05
  region net VDD_RF_1250: 33.35,14.234 34.025,14.234 34.025,11.625 30.35,11.625 30.35,9.275 29.7,9.275 29.7,12.225 33.35,12.225
  region net VDD_RF_1250: 29,9.925 30.129,9.925 30.129,9.275 29,9.275
  pour cut-out: 69.5,1.325 72.725,1.325 72.725,0.2 69.5,0.2
  region net VDD_RF_1250: 33.537,20.675 34.036,20.675 34.036,17.28 34.773,16.543 34.773,15.464 34.036,14.728 34.036,13.725 33.357,13.725 33.35,14.718 34.325,15.693 34.325,16.283 33.538,17.07
  text "4" at 72,0.4 h0.76

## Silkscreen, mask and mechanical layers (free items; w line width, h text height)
Top Overlay:
  lines w0.254: -0.001,31.725 -0.001,32.233 ; 1.523,31.471 -0.001,31.979 ; 1.523,32.487 -0.001,31.979 ; 29.212,31.979 -0.001,31.979 ; 43.736,31.979 72.949,31.979 ; 71.425,31.471 72.949,31.979 ; 71.425,32.487 72.949,31.979 ; 72.949,31.725 72.949,32.233 ; 78.181,1.51 78.689,-0.014 ; 78.181,29.362 78.689,30.886 ; 78.435,-0.014 78.943,-0.014 ; 78.435,30.886 78.943,30.886 ; 78.689,8.936 78.689,-0.014 ; 78.689,21.937 78.689,30.886 ; 79.197,1.51 78.689,-0.014 ; 79.197,29.362 78.689,30.886
  text "72.95 (mm)" at 29.466,31.064 h1.52
  text "30.9 (mm)" at 79.603,9.19 h1.52 r90
  text "PCB_E616V01A" at 16.586,2.134 h0.8
  text "CoreCell Gateway 2*SX1250 Front-Ends" at 5.893,0.838 h0.8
